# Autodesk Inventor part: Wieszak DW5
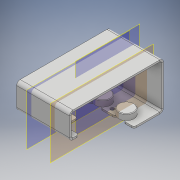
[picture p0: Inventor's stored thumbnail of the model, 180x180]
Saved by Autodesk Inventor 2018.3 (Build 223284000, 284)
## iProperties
Created: 2021-04
Part Number: Wieszak DW5
Material: Ogólny
Document SubType Name: Modeling
Designer: Verical
Density: 1 g/cm^3
Appearance: Domyślna
Author: Verical
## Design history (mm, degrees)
derived "Wieszak DW5.iam"
node "Bryła1"
node "Haczyk zakryty.ipt:1"
node "Płaszczyzna konstrukcyjna1"
node "Płaszczyzna konstrukcyjna2"
node "Płaszczyzna konstrukcyjna3"
node "Kapselek.ipt:1"
node "Kapselek.ipt:2"
